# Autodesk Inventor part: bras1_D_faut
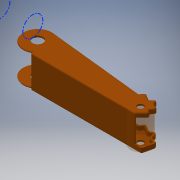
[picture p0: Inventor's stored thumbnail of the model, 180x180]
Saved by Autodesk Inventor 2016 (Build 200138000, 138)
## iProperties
Created: 2011-10
Part Number: bras1_D_faut
Document SubType Name: Modeling
Designer: Bruno
Material: Générique
Mass: 31.6122 g
Surface Area: 330.493 cm^2
Volume: 31.6122 cm^3
Density: 1 g/cm^3
Appearance: Orange (foncé)
Author: Bruno
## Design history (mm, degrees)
feature "Base1"
sketch "Esquisse1"
  geometry: C1 r 4 at (131.795, 9) reference; C2 r 13.134 at (131.795, 9)
  constraints: 1 centre point, 1 coincident
  dimensions: "d0" = 26.269 diameter of C2
feature "SrfExtrusion1" sketch "Esquisse1" dims "d1" = 45, "d2" = 0
sketch "Esquisse2"
  geometry: C1 r 4 at (131.795, 9) reference; C2 r 13.134 at (131.795, 9); 1 further point
  constraints: 1 centre point, 1 coincident
  dimensions: "d3" = 26.269 diameter of C2
feature "SrfExtrusion2" sketch "Esquisse2" dims "d4" = 10, "d5" = 0
node "Solide1"
node "Corps solides"
node "Corps surfaciques"
body "Srf1"
node "Référence1"
body "Srf2"
